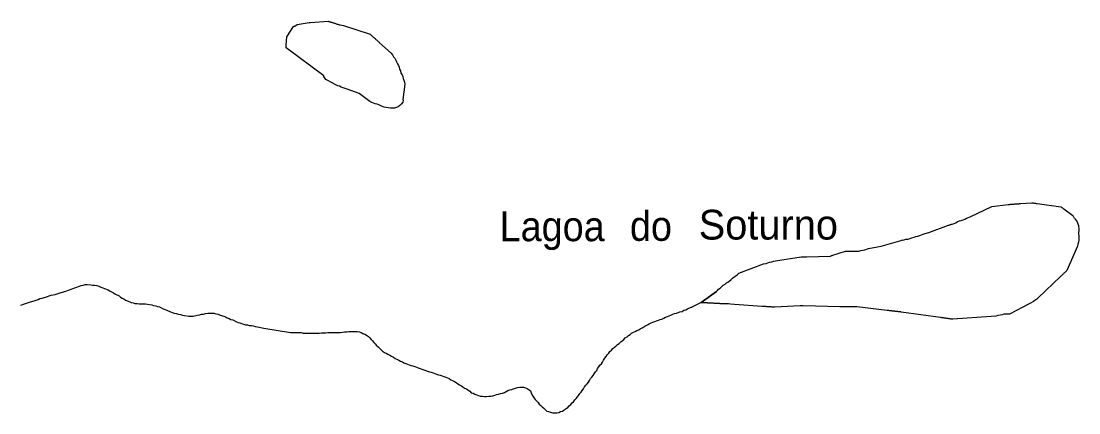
# Model space of a CAD drawing. Extents: x 785.9 to 812.4, y 7674.9 to 7703.1.
# Drawn here: x 793.585 to 796.431, y 7691.131 to 7692.184 of the extents above; entities that cross this region are included whole.
import ezdxf
from ezdxf.enums import TextEntityAlignment as Align

# ---------------------------------------------------------------- set-up
doc = ezdxf.new("R2010")
doc.units = 0
doc.header["$LTSCALE"] = 0.04
doc.linetypes.add('LONG_DASHED', pattern=[7.5, 6, -1.5])
doc.layers.add('3', color=7, linetype='LONG_DASHED', lineweight=25)
doc.layers.add('7', color=7, linetype='Continuous', lineweight=25)
doc.layers.add('61', color=7, linetype='Continuous')

msp = doc.modelspace()

# ---------------------------------------------------------------- linework, layer by layer
at = {"layer": '3'}
for points in [[(794.3998, 7692.0371), (794.2981, 7692.1128), (794.2982, 7692.1136), (794.2983, 7692.1152), (794.2984, 7692.1168), (794.2986, 7692.1185), (794.2987, 7692.1201), (794.2987, 7692.1201), (794.3003, 7692.1419), (794.3003, 7692.1419), (794.3182, 7692.1703), (794.3198, 7692.1707), (794.3213, 7692.171), (794.3278, 7692.1751), (794.3602, 7692.1808), (794.3642, 7692.1808), (794.4111, 7692.1844), (794.4126, 7692.1839), (794.4141, 7692.1834), (794.4157, 7692.1829), (794.4172, 7692.1824), (794.4188, 7692.182), (794.4203, 7692.1815), (794.4219, 7692.181), (794.4234, 7692.1805), (794.425, 7692.18), (794.4265, 7692.1796), (794.4281, 7692.1791), (794.4296, 7692.1786), (794.4311, 7692.1781), (794.4327, 7692.1776), (794.4342, 7692.1772), (794.4358, 7692.1767), (794.4373, 7692.1762), (794.4389, 7692.1757), (794.4404, 7692.1752), (794.442, 7692.1748), (794.4435, 7692.1743), (794.4524, 7692.1727), (794.5242, 7692.1492), (794.5254, 7692.1482), (794.5266, 7692.1471), (794.5278, 7692.146), (794.529, 7692.1449), (794.5302, 7692.1438), (794.5314, 7692.1428), (794.5326, 7692.1417), (794.5338, 7692.1406), (794.5351, 7692.1395), (794.5363, 7692.1384), (794.5375, 7692.1374), (794.5387, 7692.1363), (794.5399, 7692.1352), (794.5411, 7692.1341), (794.5423, 7692.133), (794.5435, 7692.1319), (794.5447, 7692.1309), (794.5459, 7692.1298), (794.5471, 7692.1287), (794.5483, 7692.1276), (794.5495, 7692.1265), (794.5495, 7692.1265), (794.5811, 7692.0982), (794.5843, 7692.0934), (794.5875, 7692.0885), (794.5908, 7692.0845), (794.5932, 7692.0796), (794.5948, 7692.0748), (794.5981, 7692.0699), (794.6005, 7692.065), (794.6021, 7692.0602), (794.6037, 7692.0553), (794.6061, 7692.0505), (794.607, 7692.0448), (794.6102, 7692.04), (794.6118, 7692.0351), (794.6134, 7692.0303), (794.615, 7692.0254), (794.6167, 7692.0205), (794.6175, 7692.0149), (794.6124, 7691.974), (794.6126, 7691.9736), (794.6134, 7691.972), (794.6126, 7691.9663), (794.6086, 7691.9615), (794.6045, 7691.9574), (794.5997, 7691.9542), (794.5948, 7691.9518), (794.59, 7691.9501), (794.5786, 7691.9501), (794.573, 7691.951), (794.5673, 7691.9518), (794.5616, 7691.9534), (794.5552, 7691.9558), (794.5479, 7691.9591), (794.543, 7691.9607), (794.5382, 7691.9623), (794.5333, 7691.9639), (794.5285, 7691.9655), (794.5236, 7691.968), (794.495, 7691.9899)], [(794.495, 7691.9899), (794.4629, 7692.0011), (794.4467, 7692.0068), (794.4419, 7692.0092), (794.437, 7692.0108), (794.4322, 7692.0133), (794.42, 7692.0189), (794.4103, 7692.0246), (794.4055, 7692.027), (794.3998, 7692.0351), (794.3998, 7692.0371)], [(795.8994, 7691.5791), (795.8994, 7691.5791), (795.9558, 7691.5949), (795.955, 7691.5949), (795.9607, 7691.5957), (795.9655, 7691.5974), (795.9712, 7691.5982), (795.976, 7691.5998), (795.9817, 7691.6014), (795.9874, 7691.603), (795.9922, 7691.6046), (795.9979, 7691.6063), (796.0027, 7691.6079), (796.0076, 7691.6095), (796.0124, 7691.6111), (796.0173, 7691.6127), (796.027, 7691.616), (796.0805, 7691.6354), (796.0809, 7691.6356), (796.0824, 7691.6361), (796.084, 7691.6366), (796.0855, 7691.6371), (796.087, 7691.6376), (796.0886, 7691.6381), (796.0901, 7691.6386), (796.095, 7691.6402), (796.0998, 7691.6419), (796.1047, 7691.6451), (796.1095, 7691.6467), (796.1144, 7691.6483), (796.1192, 7691.65), (796.1241, 7691.6516), (796.129, 7691.654), (796.1387, 7691.658), (796.1969, 7691.6856), (796.1969, 7691.6856), (796.2407, 7691.6912), (796.2423, 7691.6913), (796.2439, 7691.6914), (796.2455, 7691.6915), (796.2472, 7691.6917), (796.2488, 7691.6918), (796.2504, 7691.6919), (796.252, 7691.692), (796.2536, 7691.6921), (796.2552, 7691.6922), (796.2568, 7691.6924), (796.2585, 7691.6925), (796.2601, 7691.6926), (796.2617, 7691.6927), (796.2633, 7691.6928), (796.2649, 7691.6929), (796.2665, 7691.6931), (796.2681, 7691.6932), (796.2698, 7691.6933), (796.2714, 7691.6934), (796.273, 7691.6935), (796.2746, 7691.6937), (796.2746, 7691.6937), (796.3039, 7691.6958), (796.3047, 7691.6957), (796.3063, 7691.6954), (796.3079, 7691.6952), (796.3095, 7691.695), (796.3111, 7691.6948), (796.3127, 7691.6945), (796.3143, 7691.6943), (796.3159, 7691.6941), (796.3175, 7691.6939), (796.3191, 7691.6937), (796.3191, 7691.6937), (796.3825, 7691.6848), (796.3838, 7691.6839), (796.3851, 7691.6829), (796.3864, 7691.682), (796.3877, 7691.681), (796.389, 7691.68), (796.3903, 7691.6791), (796.3903, 7691.6791), (796.4145, 7691.6613), (796.4148, 7691.661), (796.4157, 7691.6597), (796.4166, 7691.6583), (796.4175, 7691.657), (796.4184, 7691.6556), (796.4193, 7691.6543), (796.4202, 7691.6529)], [(795.8994, 7691.5791), (795.8994, 7691.5791), (795.9558, 7691.5949), (795.955, 7691.5949), (795.9607, 7691.5957), (795.9655, 7691.5974), (795.9712, 7691.5982), (795.976, 7691.5998), (795.9817, 7691.6014), (795.9874, 7691.603), (795.9922, 7691.6046), (795.9979, 7691.6063), (796.0027, 7691.6079), (796.0076, 7691.6095), (796.0124, 7691.6111), (796.0173, 7691.6127), (796.027, 7691.616), (796.0805, 7691.6354), (796.0809, 7691.6356), (796.0824, 7691.6361), (796.084, 7691.6366), (796.0855, 7691.6371), (796.087, 7691.6376), (796.0886, 7691.6381), (796.0901, 7691.6386), (796.095, 7691.6402), (796.0998, 7691.6419), (796.1047, 7691.6451), (796.1095, 7691.6467), (796.1144, 7691.6483), (796.1192, 7691.65), (796.1241, 7691.6516), (796.129, 7691.654), (796.1387, 7691.658), (796.1969, 7691.6856), (796.1969, 7691.6856), (796.2407, 7691.6912), (796.2423, 7691.6913), (796.2439, 7691.6914), (796.2455, 7691.6915), (796.2472, 7691.6917), (796.2488, 7691.6918), (796.2504, 7691.6919), (796.252, 7691.692), (796.2536, 7691.6921), (796.2552, 7691.6922), (796.2568, 7691.6924), (796.2585, 7691.6925), (796.2601, 7691.6926), (796.2617, 7691.6927), (796.2633, 7691.6928), (796.2649, 7691.6929), (796.2665, 7691.6931), (796.2681, 7691.6932), (796.2698, 7691.6933), (796.2714, 7691.6934), (796.273, 7691.6935), (796.2746, 7691.6937), (796.2746, 7691.6937), (796.3039, 7691.6958), (796.3047, 7691.6957), (796.3063, 7691.6954), (796.3079, 7691.6952), (796.3095, 7691.695), (796.3111, 7691.6948), (796.3127, 7691.6945), (796.3143, 7691.6943), (796.3159, 7691.6941), (796.3175, 7691.6939), (796.3191, 7691.6937), (796.3191, 7691.6937), (796.3825, 7691.6848), (796.3838, 7691.6839), (796.3851, 7691.6829), (796.3864, 7691.682), (796.3877, 7691.681), (796.389, 7691.68), (796.3903, 7691.6791), (796.3903, 7691.6791), (796.4145, 7691.6613), (796.4148, 7691.661), (796.4157, 7691.6597), (796.4166, 7691.6583), (796.4175, 7691.657), (796.4184, 7691.6556), (796.4193, 7691.6543), (796.4202, 7691.6529)], [(796.4202, 7691.6529), (796.4211, 7691.6516), (796.4259, 7691.6443), (796.4283, 7691.6394), (796.43, 7691.6346), (796.4308, 7691.6241), (796.43, 7691.6119), (796.4308, 7691.6063), (796.4308, 7691.6006), (796.4308, 7691.5949), (796.43, 7691.5893), (796.4283, 7691.5844), (796.4275, 7691.5788), (796.3989, 7691.5138), (796.3978, 7691.5127), (796.3966, 7691.5116), (796.3954, 7691.5105), (796.3943, 7691.5094), (796.3931, 7691.5082), (796.3919, 7691.5071), (796.3907, 7691.506), (796.3896, 7691.5049), (796.3884, 7691.5038), (796.3872, 7691.5026), (796.3861, 7691.5015), (796.3849, 7691.5004), (796.3837, 7691.4993), (796.3826, 7691.4981), (796.3814, 7691.497), (796.3814, 7691.497), (796.3215, 7691.4396), (796.3175, 7691.4363), (796.3126, 7691.4331), (796.3086, 7691.4299), (796.2989, 7691.425), (796.2439, 7691.3959), (796.243, 7691.3959), (796.2414, 7691.3959), (796.2398, 7691.3959), (796.2382, 7691.3959), (796.2366, 7691.3959), (796.235, 7691.3959), (796.2333, 7691.3959), (796.2317, 7691.3959), (796.2301, 7691.3959), (796.2293, 7691.3959), (796.2244, 7691.3943), (796.2188, 7691.3935), (796.2131, 7691.3926), (796.2083, 7691.391), (796.1953, 7691.3894), (796.0922, 7691.3823), (796.0906, 7691.3825), (796.089, 7691.3827), (796.0874, 7691.3829), (796.0858, 7691.3832), (796.0842, 7691.3834), (796.0826, 7691.3836), (796.081, 7691.3838), (796.0794, 7691.3841), (796.0778, 7691.3843), (796.0762, 7691.3845), (796.0746, 7691.3847), (796.073, 7691.385), (796.0714, 7691.3852), (796.0698, 7691.3854), (796.0682, 7691.3856), (796.0666, 7691.3859), (796.065, 7691.3861), (796.0634, 7691.3863), (796.0618, 7691.3865), (796.0602, 7691.3868), (796.0586, 7691.387), (796.0586, 7691.387), (795.9532, 7691.4018), (795.9515, 7691.402), (795.9499, 7691.4021), (795.9483, 7691.4023), (795.9467, 7691.4025), (795.9451, 7691.4027), (795.9435, 7691.4029), (795.9419, 7691.403), (795.9403, 7691.4032), (795.9387, 7691.4034), (795.9371, 7691.4036), (795.9355, 7691.4038), (795.9339, 7691.404), (795.9323, 7691.4041), (795.9306, 7691.4043), (795.929, 7691.4045), (795.9274, 7691.4047), (795.9258, 7691.4049), (795.9242, 7691.4051), (795.9226, 7691.4052), (795.921, 7691.4054), (795.9194, 7691.4056), (795.9153, 7691.4056), (795.8336, 7691.4153), (795.832, 7691.4153), (795.8304, 7691.4153), (795.8288, 7691.4153)], [(796.4202, 7691.6529), (796.4211, 7691.6516), (796.4259, 7691.6443), (796.4283, 7691.6394), (796.43, 7691.6346), (796.4308, 7691.6241), (796.43, 7691.6119), (796.4308, 7691.6063), (796.4308, 7691.6006), (796.4308, 7691.5949), (796.43, 7691.5893), (796.4283, 7691.5844), (796.4275, 7691.5788), (796.3989, 7691.5138), (796.3978, 7691.5127), (796.3966, 7691.5116), (796.3954, 7691.5105), (796.3943, 7691.5094), (796.3931, 7691.5082), (796.3919, 7691.5071), (796.3907, 7691.506), (796.3896, 7691.5049), (796.3884, 7691.5038), (796.3872, 7691.5026), (796.3861, 7691.5015), (796.3849, 7691.5004), (796.3837, 7691.4993), (796.3826, 7691.4981), (796.3814, 7691.497), (796.3814, 7691.497), (796.3215, 7691.4396), (796.3175, 7691.4363), (796.3126, 7691.4331), (796.3086, 7691.4299), (796.2989, 7691.425), (796.2439, 7691.3959), (796.243, 7691.3959), (796.2414, 7691.3959), (796.2398, 7691.3959), (796.2382, 7691.3959), (796.2366, 7691.3959), (796.235, 7691.3959), (796.2333, 7691.3959), (796.2317, 7691.3959), (796.2301, 7691.3959), (796.2293, 7691.3959), (796.2244, 7691.3943), (796.2188, 7691.3935), (796.2131, 7691.3926), (796.2083, 7691.391), (796.1953, 7691.3894), (796.0922, 7691.3823), (796.0906, 7691.3825), (796.089, 7691.3827), (796.0874, 7691.3829), (796.0858, 7691.3832), (796.0842, 7691.3834), (796.0826, 7691.3836), (796.081, 7691.3838), (796.0794, 7691.3841), (796.0778, 7691.3843), (796.0762, 7691.3845), (796.0746, 7691.3847), (796.073, 7691.385), (796.0714, 7691.3852), (796.0698, 7691.3854), (796.0682, 7691.3856), (796.0666, 7691.3859), (796.065, 7691.3861), (796.0634, 7691.3863), (796.0618, 7691.3865), (796.0602, 7691.3868), (796.0586, 7691.387), (796.0586, 7691.387), (795.9532, 7691.4018), (795.9515, 7691.402), (795.9499, 7691.4021), (795.9483, 7691.4023), (795.9467, 7691.4025), (795.9451, 7691.4027), (795.9435, 7691.4029), (795.9419, 7691.403), (795.9403, 7691.4032), (795.9387, 7691.4034), (795.9371, 7691.4036), (795.9355, 7691.4038), (795.9339, 7691.404), (795.9323, 7691.4041), (795.9306, 7691.4043), (795.929, 7691.4045), (795.9274, 7691.4047), (795.9258, 7691.4049), (795.9242, 7691.4051), (795.9226, 7691.4052), (795.921, 7691.4054), (795.9194, 7691.4056), (795.9153, 7691.4056), (795.8336, 7691.4153), (795.832, 7691.4153), (795.8304, 7691.4153), (795.8288, 7691.4153)], [(795.4561, 7691.4566), (795.4574, 7691.459), (795.4614, 7691.463), (795.4663, 7691.4663), (795.4703, 7691.4703), (795.4744, 7691.4744), (795.4792, 7691.4768), (795.4833, 7691.48), (795.4881, 7691.4833), (795.4954, 7691.4889), (795.4994, 7691.493), (795.5035, 7691.4962), (795.5083, 7691.4995), (795.5124, 7691.5027), (795.5164, 7691.5059), (795.5828, 7691.5318), (795.5893, 7691.5326), (795.5941, 7691.5343), (795.599, 7691.5359), (795.6046, 7691.5367), (795.6103, 7691.5383), (795.6151, 7691.5399), (795.6835, 7691.55), (795.6839, 7691.55), (795.6856, 7691.55), (795.6872, 7691.5501), (795.6888, 7691.5501), (795.6904, 7691.5502), (795.692, 7691.5502), (795.6936, 7691.5503), (795.6953, 7691.5503), (795.6969, 7691.5504), (795.6985, 7691.5504), (795.6985, 7691.5504), (795.7627, 7691.5524), (795.7643, 7691.5529), (795.7658, 7691.5535), (795.7674, 7691.554), (795.7689, 7691.5545), (795.7689, 7691.5545), (795.8029, 7691.5658), (795.8393, 7691.5658), (795.8441, 7691.5674), (795.8498, 7691.5682), (795.8555, 7691.569), (795.8652, 7691.5723), (795.8894, 7691.5771), (795.899, 7691.579), (795.8994, 7691.5791)], [(795.4561, 7691.4566), (795.4574, 7691.459), (795.4614, 7691.463), (795.4663, 7691.4663), (795.4703, 7691.4703), (795.4744, 7691.4744), (795.4792, 7691.4768), (795.4833, 7691.48), (795.4881, 7691.4833), (795.4954, 7691.4889), (795.4994, 7691.493), (795.5035, 7691.4962), (795.5083, 7691.4995), (795.5124, 7691.5027), (795.5164, 7691.5059), (795.5828, 7691.5318), (795.5893, 7691.5326), (795.5941, 7691.5343), (795.599, 7691.5359), (795.6046, 7691.5367), (795.6103, 7691.5383), (795.6151, 7691.5399), (795.6835, 7691.55), (795.6839, 7691.55), (795.6856, 7691.55), (795.6872, 7691.5501), (795.6888, 7691.5501), (795.6904, 7691.5502), (795.692, 7691.5502), (795.6936, 7691.5503), (795.6953, 7691.5503), (795.6969, 7691.5504), (795.6985, 7691.5504), (795.6985, 7691.5504), (795.7627, 7691.5524), (795.7643, 7691.5529), (795.7658, 7691.5535), (795.7674, 7691.554), (795.7689, 7691.5545), (795.7689, 7691.5545), (795.8029, 7691.5658), (795.8393, 7691.5658), (795.8441, 7691.5674), (795.8498, 7691.5682), (795.8555, 7691.569), (795.8652, 7691.5723), (795.8894, 7691.5771), (795.899, 7691.579), (795.8994, 7691.5791)], [(795.4561, 7691.4566), (795.4152, 7691.4272), (795.4819, 7691.4235)], [(795.4819, 7691.4235), (795.4152, 7691.4272), (795.4561, 7691.4566)], [(795.8288, 7691.4153), (795.8271, 7691.4153), (795.8255, 7691.4153), (795.8239, 7691.4153), (795.8223, 7691.4153), (795.8207, 7691.4153), (795.8191, 7691.4153), (795.8174, 7691.4153), (795.8158, 7691.4153), (795.8142, 7691.4153), (795.8126, 7691.4153), (795.811, 7691.4153), (795.8093, 7691.4153), (795.8077, 7691.4153), (795.8061, 7691.4153), (795.8045, 7691.4153), (795.8029, 7691.4153), (795.8013, 7691.4153), (795.7996, 7691.4153), (795.7988, 7691.4153), (795.7875, 7691.4153), (795.6896, 7691.4185), (795.6807, 7691.4185), (795.6126, 7691.4147), (795.611, 7691.4148), (795.6094, 7691.4149), (795.6078, 7691.415), (795.6062, 7691.4151), (795.6046, 7691.4152), (795.603, 7691.4153), (795.6013, 7691.4154), (795.5997, 7691.4156), (795.5981, 7691.4157), (795.5965, 7691.4158), (795.5949, 7691.4159), (795.5933, 7691.416), (795.5917, 7691.4161), (795.59, 7691.4162), (795.5884, 7691.4163), (795.5868, 7691.4164), (795.5852, 7691.4165), (795.5836, 7691.4166), (795.582, 7691.4167), (795.5804, 7691.4168), (795.5787, 7691.4169), (795.5787, 7691.4169), (795.5043, 7691.4218), (795.4938, 7691.4226), (795.4881, 7691.4234), (795.4824, 7691.4234), (795.4819, 7691.4235)], [(795.8288, 7691.4153), (795.8271, 7691.4153), (795.8255, 7691.4153), (795.8239, 7691.4153), (795.8223, 7691.4153), (795.8207, 7691.4153), (795.8191, 7691.4153), (795.8174, 7691.4153), (795.8158, 7691.4153), (795.8142, 7691.4153), (795.8126, 7691.4153), (795.811, 7691.4153), (795.8093, 7691.4153), (795.8077, 7691.4153), (795.8061, 7691.4153), (795.8045, 7691.4153), (795.8029, 7691.4153), (795.8013, 7691.4153), (795.7996, 7691.4153), (795.7988, 7691.4153), (795.7875, 7691.4153), (795.6896, 7691.4185), (795.6807, 7691.4185), (795.6126, 7691.4147), (795.611, 7691.4148), (795.6094, 7691.4149), (795.6078, 7691.415), (795.6062, 7691.4151), (795.6046, 7691.4152), (795.603, 7691.4153), (795.6013, 7691.4154), (795.5997, 7691.4156), (795.5981, 7691.4157), (795.5965, 7691.4158), (795.5949, 7691.4159), (795.5933, 7691.416), (795.5917, 7691.4161), (795.59, 7691.4162), (795.5884, 7691.4163), (795.5868, 7691.4164), (795.5852, 7691.4165), (795.5836, 7691.4166), (795.582, 7691.4167), (795.5804, 7691.4168), (795.5787, 7691.4169), (795.5787, 7691.4169), (795.5043, 7691.4218), (795.4938, 7691.4226), (795.4881, 7691.4234), (795.4824, 7691.4234), (795.4819, 7691.4235)]]:
    msp.add_lwpolyline(points, dxfattribs=at)
at = {"layer": '7'}
msp.add_line((795.4152, 7691.4272), (795.3931, 7691.4167), dxfattribs=at)
for points in [[(793.585, 7691.4202), (793.5947, 7691.4234), (793.5996, 7691.4258), (793.6052, 7691.4274), (793.6109, 7691.4291), (793.6206, 7691.4323), (793.6255, 7691.4339), (793.6311, 7691.4355), (793.636, 7691.438), (793.6416, 7691.4388), (793.6562, 7691.4436), (793.6611, 7691.4452), (793.6659, 7691.4469), (793.6716, 7691.4477), (793.6773, 7691.4493), (793.6821, 7691.4509), (793.6878, 7691.4525), (793.7023, 7691.4574), (793.708, 7691.459), (793.7177, 7691.4622), (793.7226, 7691.4639), (793.7274, 7691.4663), (793.7323, 7691.4679), (793.742, 7691.4711), (793.7468, 7691.4728), (793.7525, 7691.4744), (793.7574, 7691.476), (793.763, 7691.476), (793.7727, 7691.4752), (793.7776, 7691.4736), (793.7832, 7691.4736), (793.7889, 7691.4728), (793.7946, 7691.4711), (793.7994, 7691.4687), (793.8051, 7691.4671), (793.81, 7691.4647), (793.8197, 7691.4614), (793.8245, 7691.4582), (793.8342, 7691.4533), (793.8391, 7691.4501), (793.8488, 7691.4452), (793.8528, 7691.442), (793.8569, 7691.4388), (793.8617, 7691.4372), (793.8666, 7691.4339), (793.8714, 7691.4323), (793.8812, 7691.4274), (793.8868, 7691.4266), (793.8917, 7691.425), (793.8973, 7691.425), (793.903, 7691.4242), (793.9087, 7691.4242), (793.9143, 7691.4234), (793.92, 7691.4234), (793.9257, 7691.4226), (793.937, 7691.421), (793.9418, 7691.4194), (793.9475, 7691.4185), (793.9524, 7691.4169), (793.958, 7691.4153), (793.9677, 7691.4105), (793.9726, 7691.4088), (793.9774, 7691.4072), (793.9872, 7691.4024), (793.992, 7691.4007), (793.9969, 7691.3983), (794.0025, 7691.3975), (794.0082, 7691.3959), (794.0139, 7691.3951), (794.0195, 7691.3935), (794.0252, 7691.3926), (794.0365, 7691.391), (794.0478, 7691.391), (794.0592, 7691.3935), (794.0648, 7691.3943), (794.0705, 7691.3959), (794.0762, 7691.3959), (794.0818, 7691.3975), (794.0875, 7691.3983), (794.1045, 7691.3983), (794.1093, 7691.3967), (794.1158, 7691.3959), (794.1207, 7691.3935), (794.1304, 7691.3902), (794.1352, 7691.3886), (794.1401, 7691.3862), (794.1449, 7691.3846), (794.1498, 7691.3821), (794.1546, 7691.3805), (794.1644, 7691.3757), (794.1692, 7691.374), (794.1741, 7691.3724), (794.1838, 7691.3692), (794.1886, 7691.3676), (794.1943, 7691.3676), (794.1991, 7691.3659), (794.2048, 7691.3651), (794.2105, 7691.3643), (794.2153, 7691.3627), (794.221, 7691.3619), (794.238, 7691.3587)], [(795.2373, 7691.349), (795.2421, 7691.3522), (795.247, 7691.3538), (795.251, 7691.357), (795.2559, 7691.3595), (795.2607, 7691.3619), (795.2656, 7691.3651), (795.2705, 7691.3676), (795.2753, 7691.37), (795.2802, 7691.3724), (795.285, 7691.3748), (795.2899, 7691.3765), (795.2947, 7691.3781), (795.2996, 7691.3797), (795.3044, 7691.3813), (795.3093, 7691.3829), (795.3141, 7691.3854), (795.319, 7691.3878), (795.3239, 7691.3894), (795.3287, 7691.3918), (795.3336, 7691.3935), (795.3384, 7691.3959), (795.3433, 7691.3975), (795.3481, 7691.3991), (795.353, 7691.4007), (795.3578, 7691.4024), (795.3635, 7691.4032), (795.3684, 7691.4064), (795.3732, 7691.408), (795.3781, 7691.4105), (795.3878, 7691.4145), (795.3893, 7691.4151), (795.3908, 7691.4157), (795.3923, 7691.4164), (795.3931, 7691.4167)], [(794.238, 7691.3587), (794.31, 7691.3465), (794.3213, 7691.3465), (794.327, 7691.3465), (794.3327, 7691.3465), (794.3383, 7691.3465), (794.344, 7691.3449), (794.3496, 7691.3449), (794.3553, 7691.3449), (794.3642, 7691.3449), (794.3699, 7691.3449), (794.3755, 7691.3449), (794.3812, 7691.3449), (794.3869, 7691.3449), (794.3933, 7691.3457), (794.399, 7691.3457), (794.4047, 7691.3457), (794.4103, 7691.3465), (794.416, 7691.3465), (794.4217, 7691.3465), (794.4273, 7691.3465), (794.4387, 7691.3465), (794.4443, 7691.3465), (794.45, 7691.3473), (794.4556, 7691.3481), (794.4613, 7691.3481), (794.467, 7691.349), (794.4726, 7691.3498), (794.4783, 7691.3498), (794.484, 7691.3498), (794.4896, 7691.349), (794.4953, 7691.3481), (794.5001, 7691.3465), (794.505, 7691.3441), (794.5099, 7691.3425), (794.5147, 7691.3392), (794.5196, 7691.336), (794.5236, 7691.332), (794.5269, 7691.3279), (794.5309, 7691.3239), (794.5341, 7691.3198), (794.5382, 7691.3158), (794.5414, 7691.3117), (794.5455, 7691.3077), (794.5495, 7691.3045), (794.5536, 7691.3004), (794.5576, 7691.2964), (794.5625, 7691.2931), (794.5673, 7691.2907), (794.5722, 7691.2883), (794.577, 7691.2858), (794.5819, 7691.2826), (794.5867, 7691.2802), (794.5916, 7691.2769), (794.5964, 7691.2745), (794.6013, 7691.2721), (794.6061, 7691.2697), (794.611, 7691.268), (794.615, 7691.2648), (794.6199, 7691.2632), (794.6248, 7691.2616), (794.6296, 7691.26), (794.6345, 7691.2583), (794.6393, 7691.2567), (794.6442, 7691.2551), (794.649, 7691.2535), (794.6539, 7691.2519), (794.6587, 7691.2494), (794.6636, 7691.2478), (794.6685, 7691.2462), (794.6741, 7691.2446), (794.679, 7691.243), (794.6838, 7691.2413), (794.6887, 7691.2397), (794.6935, 7691.2381), (794.6984, 7691.2365), (794.7032, 7691.2349), (794.7081, 7691.2332), (794.713, 7691.2316), (794.7178, 7691.23), (794.7227, 7691.2284), (794.7275, 7691.2268), (794.7324, 7691.2243), (794.7372, 7691.2227), (794.7413, 7691.2195), (794.7461, 7691.2171), (794.751, 7691.2146), (794.7558, 7691.2122), (794.7599, 7691.209), (794.7647, 7691.2057), (794.7696, 7691.2033), (794.7736, 7691.2001), (794.7785, 7691.1968), (794.7833, 7691.1952), (794.7874, 7691.192), (794.7923, 7691.1887), (794.7963, 7691.1847), (794.8012, 7691.1831), (794.806, 7691.1807), (794.8109, 7691.179), (794.8157, 7691.1774)], [(794.8157, 7691.1774), (794.8206, 7691.1758), (794.8262, 7691.175), (794.8319, 7691.1742), (794.8376, 7691.1742), (794.8432, 7691.175), (794.8489, 7691.1758), (794.8546, 7691.1766), (794.8594, 7691.1782), (794.8643, 7691.1798), (794.8699, 7691.1807), (794.8748, 7691.1823), (794.8804, 7691.1839), (794.8853, 7691.1855), (794.8902, 7691.1879), (794.895, 7691.1904), (794.8999, 7691.192), (794.9047, 7691.1936), (794.9096, 7691.1952), (794.9152, 7691.1968), (794.9209, 7691.1985), (794.9266, 7691.1993), (794.9371, 7691.1993), (794.9419, 7691.1976), (794.9468, 7691.196), (794.9517, 7691.1928), (794.9557, 7691.1896), (794.9573, 7691.1847), (794.9597, 7691.1798), (794.9622, 7691.175), (794.9654, 7691.1701), (794.9686, 7691.1661), (794.9727, 7691.162), (794.9759, 7691.158), (794.9792, 7691.154), (794.9832, 7691.1499), (794.9873, 7691.1467), (794.9913, 7691.1434), (794.9953, 7691.1394), (794.9994, 7691.1353), (795.0042, 7691.1337), (795.0091, 7691.1321), (795.0148, 7691.1305), (795.0204, 7691.1305), (795.0261, 7691.1305), (795.0318, 7691.1313), (795.0366, 7691.1337), (795.0415, 7691.1353), (795.0463, 7691.1386), (795.0512, 7691.1418), (795.056, 7691.1451), (795.0601, 7691.1491), (795.0641, 7691.1531), (795.0674, 7691.1572), (795.0714, 7691.1604), (795.0746, 7691.1653), (795.0787, 7691.1693), (795.0819, 7691.1734), (795.0852, 7691.1774), (795.0884, 7691.1823), (795.0916, 7691.1863), (795.0949, 7691.1904), (795.0981, 7691.1952), (795.1013, 7691.2001), (795.1046, 7691.2049), (795.1078, 7691.209), (795.1119, 7691.213), (795.1143, 7691.2179), (795.1175, 7691.2227), (795.1208, 7691.2268), (795.124, 7691.2308), (795.1272, 7691.2357), (795.1305, 7691.2405), (795.1337, 7691.2446), (795.1361, 7691.2494), (795.1394, 7691.2543), (795.1426, 7691.2591), (795.1467, 7691.2624), (795.1491, 7691.2672), (795.1523, 7691.2721), (795.1556, 7691.2778), (795.1588, 7691.2818), (795.162, 7691.2867), (795.1661, 7691.2907), (795.1693, 7691.2956), (795.1734, 7691.2996), (795.1774, 7691.3036), (795.1814, 7691.3069), (795.1855, 7691.3101), (795.1895, 7691.3142), (795.1944, 7691.3174), (795.1984, 7691.3214), (795.2025, 7691.3247), (795.2065, 7691.3279), (795.2106, 7691.332), (795.2154, 7691.3352), (795.2195, 7691.3384), (795.2235, 7691.3417), (795.2276, 7691.3449), (795.2324, 7691.3473), (795.2373, 7691.349)]]:
    msp.add_lwpolyline(points, dxfattribs=at)

# ---------------------------------------------------------------- texts
at = {"layer": '61', "width": 0.95}
for s, p in [('Lagoa', (795.014, 7691.5924)), ('do', (795.2797, 7691.5933))]:
    msp.add_text(s, height=0.08, dxfattribs=at).set_placement(p, align=Align.CENTER)
at = {"layer": '61'}
msp.add_text('Soturno', height=0.08, dxfattribs=at).set_placement((795.5955, 7691.5968), align=Align.CENTER)

doc.saveas('drawing.dxf')
